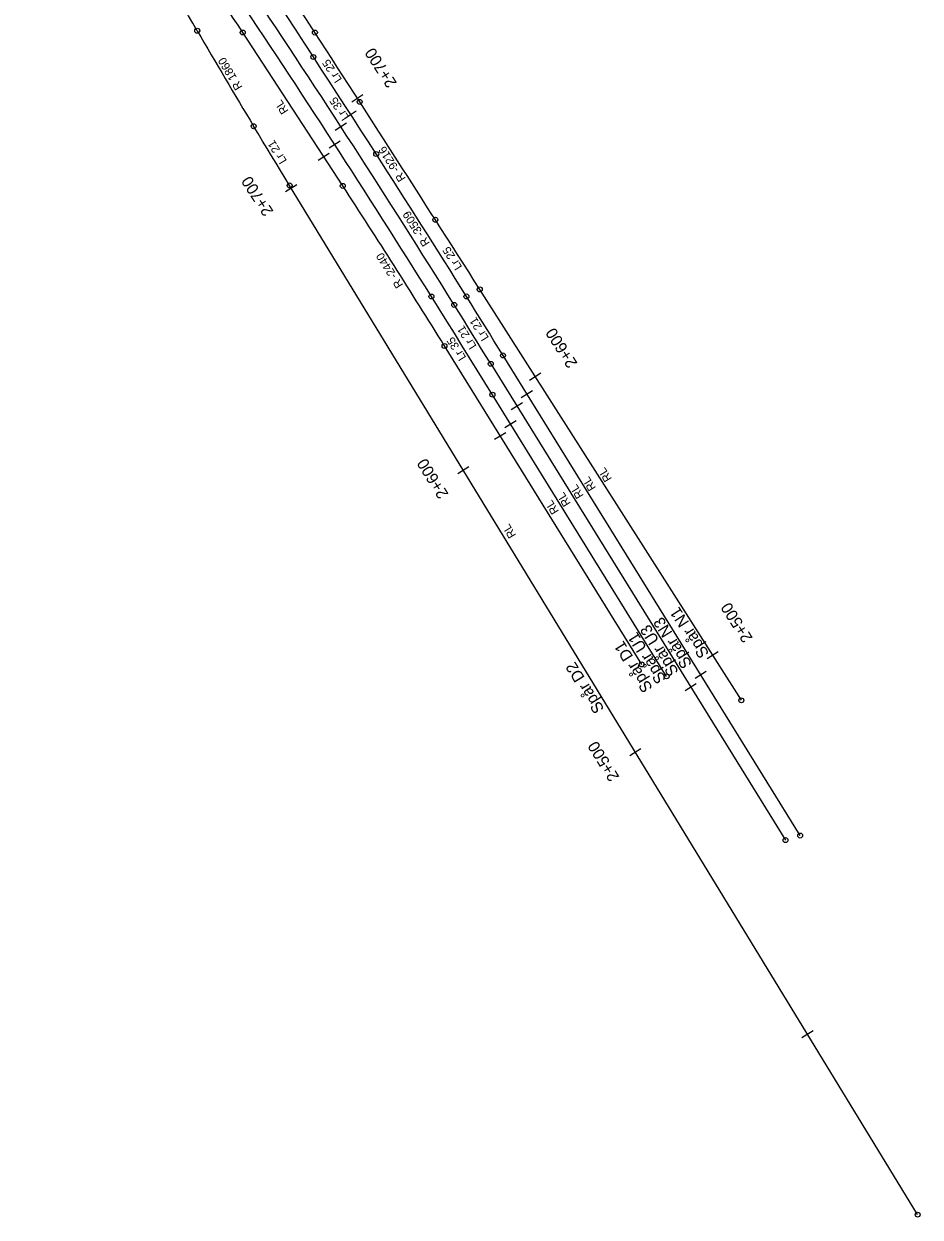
# Model space of a CAD drawing. Extents: x 149855 to 151460, y 6580726 to 6583068.
# Drawn here: x 151189 to 151460.4, y 6580725.5 to 6581086.8 of the extents above; entities that cross this region are included whole.
import ezdxf

# ---------------------------------------------------------------- set-up
doc = ezdxf.new("R2010")
doc.units = 0
for name, color, linetype in [('Hektometer L', 7, 'Continuous'), ('Hektometer T', 7, 'Continuous'), ('Modellutsnitt projekterat', 7, 'Continuous'), ('Spårgeometri T', 7, 'Continuous'), ('Spårmitt L', 7, 'Continuous'), ('Tp bef behålls P', 7, 'Continuous')]:
    doc.layers.add(name, color=color, linetype=linetype)

msp = doc.modelspace()

# ---------------------------------------------------------------- linework, layer by layer
at = {"layer": 'Hektometer L'}
for points in [[(151288.31, 6581063.21), (151291.67, 6581065.37)], [(151286.32, 6581058.25), (151289.68, 6581060.43)], [(151283.32, 6581054.6), (151286.68, 6581056.78)], [(151281.42, 6581049.24), (151284.78, 6581051.41)], [(151278.14, 6581045.51), (151281.49, 6581047.69)], [(151268.28, 6581036.03), (151271.69, 6581038.11)], [(151342.17, 6580978.96), (151345.54, 6580981.11)], [(151339.63, 6580973.7), (151343.03, 6580975.8)], [(151336.61, 6580970.03), (151340.01, 6580972.14)], [(151334.66, 6580964.64), (151338.06, 6580966.74)], [(151331.55, 6580961.02), (151334.95, 6580963.13)], [(151320.38, 6580950.67), (151323.79, 6580952.76)], [(151395.89, 6580894.62), (151399.26, 6580896.77)], [(151392.27, 6580888.67), (151395.67, 6580890.78)], [(151389.25, 6580885.01), (151392.65, 6580887.11)], [(151372.48, 6580865.32), (151375.89, 6580867.4)], [(151424.58, 6580779.96), (151427.99, 6580782.05)]]:
    msp.add_lwpolyline(points, dxfattribs=at)
at = {"layer": 'Spårmitt L'}
msp.add_line((151330.4, 6580983.87), (151419.65, 6580839.68), dxfattribs=at)
for points in [[(151277.13, 6581084.17), (151274.42, 6581088.37), (151271.7, 6581092.57), (151268.99, 6581096.77), (151266.27, 6581100.97), (151263.56, 6581105.17), (151260.86, 6581109.37), (151258.15, 6581113.58), (151255.45, 6581117.79), (151252.76, 6581122), (151250.07, 6581126.21), (151247.39, 6581130.43), (151244.71, 6581134.66), (151242.04, 6581138.89), (151239.38, 6581143.12)], [(151276.68, 6581076.77), (151273.95, 6581080.96), (151271.22, 6581085.15), (151268.5, 6581089.34), (151265.77, 6581093.54), (151263.05, 6581097.73), (151260.34, 6581101.93), (151257.62, 6581106.13), (151254.91, 6581110.33), (151252.21, 6581114.54), (151249.51, 6581118.74), (151246.82, 6581122.96), (151244.13, 6581127.17), (151241.45, 6581131.4), (151238.78, 6581135.62)], [(151241.52, 6581084.71), (151240.21, 6581086.99), (151238.9, 6581089.26), (151237.59, 6581091.54), (151236.29, 6581093.82), (151234.98, 6581096.09), (151233.68, 6581098.37), (151232.38, 6581100.65), (151231.08, 6581102.93)], [(151285.59, 6581037.74), (151255.29, 6581084.18)], [(151290.71, 6581063.18), (151289.01, 6581065.8), (151287.32, 6581068.43), (151285.62, 6581071.05), (151283.92, 6581073.68), (151282.23, 6581076.3), (151280.53, 6581078.92), (151278.83, 6581081.55), (151277.13, 6581084.17)], [(151295.72, 6581047.4), (151293.35, 6581051.08), (151290.97, 6581054.75), (151288.59, 6581058.43), (151286.21, 6581062.1), (151283.83, 6581065.77), (151281.45, 6581069.43), (151279.06, 6581073.1), (151276.68, 6581076.77)], [(151269.5, 6581037.87), (151268.13, 6581040.11), (151266.76, 6581042.35), (151265.39, 6581044.59), (151264.03, 6581046.83), (151262.67, 6581049.08), (151261.3, 6581051.32), (151259.95, 6581053.57), (151258.59, 6581055.81)], [(151459.68, 6580726.3), (151269.5, 6581037.87)], [(151327.06, 6581006.4), (151325.39, 6581009.04), (151323.71, 6581011.67), (151322.03, 6581014.31), (151320.35, 6581016.94), (151318.67, 6581019.58), (151316.99, 6581022.21), (151315.31, 6581024.85), (151313.63, 6581027.48)], [(151330.9, 6580974.52), (151328.6, 6580978.24), (151326.3, 6580981.96), (151323.99, 6580985.68), (151321.69, 6580989.4), (151319.38, 6580993.11), (151317.07, 6580996.83), (151314.75, 6581000.54), (151312.43, 6581004.25)], [(151334.11, 6580986.41), (151332.73, 6580988.64), (151331.35, 6580990.88), (151329.97, 6580993.11), (151328.58, 6580995.34), (151327.2, 6580997.57), (151325.82, 6580999.8), (151324.43, 6581002.03), (151323.04, 6581004.26)], [(151406.29, 6580882.01), (151327.06, 6581006.4)], [(151330.4, 6580983.87), (151329.02, 6580986.1), (151327.63, 6580988.33), (151326.25, 6580990.56), (151324.87, 6580992.79), (151323.49, 6580995.02), (151322.1, 6580997.25), (151320.71, 6580999.48), (151319.33, 6581001.71)], [(151376.11, 6580892.88), (151316.41, 6580989.27)], [(151424.1, 6580841.06), (151334.11, 6580986.41)], [(151383.65, 6580889.26), (151330.9, 6580974.52)], [(151459.68, 6580726.3), (151459.68, 6580726.3)]]:
    msp.add_lwpolyline(points, dxfattribs=at)
for centre, radius, start, end in [((148345.13, 6579148.16), 3504.5, 31.93168, 35.65829), ((148345.36, 6579147.78), 3500, 32.03381, 35.662), ((149580.27, 6579991.34), 2000, 33.12146, 34.32399), ((152851.64, 6582015.91), 1860, 210.04269, 211.07662), ((143546.99, 6576066.23), 9216, 32.570031, 32.833754), ((148345.03, 6579148.31), 3509, 31.93192, 32.76582), ((149242.06, 6579704.48), 2440, 31.77277, 33.12146)]:
    msp.add_arc(centre, radius, start, end, dxfattribs=at)
at = {"layer": 'Tp bef behålls P'}
for centre in [(151241.52, 6581084.71), (151255.29, 6581084.18), (151277.14, 6581084.16), (151276.68, 6581076.77), (151290.71, 6581063.17), (151258.59, 6581055.81), (151295.72, 6581047.4), (151269.5, 6581037.87), (151285.59, 6581037.74), (151313.63, 6581027.48), (151312.43, 6581004.25), (151323.04, 6581004.26), (151327.06, 6581006.4), (151319.33, 6581001.71), (151316.41, 6580989.27), (151334.11, 6580986.41), (151330.4, 6580983.87), (151330.9, 6580974.52), (151376.11, 6580892.88), (151383.65, 6580889.26), (151406.29, 6580882.01), (151424.1, 6580841.06), (151419.65, 6580839.68), (151459.68, 6580726.3)]:
    msp.add_circle(centre, 0.75, dxfattribs=at)

# ---------------------------------------------------------------- texts
at = {"layer": 'Hektometer T'}
for s, rotation, p in [('2+700', 122.8418, (151302.1, 6581068.88)), ('2+700', 122.928, (151264.73, 6581030.02)), ('2+600', 122.4923, (151356.78, 6580984.04)), ('2+600', 121.7473, (151317.72, 6580944.42)), ('2+500', 122.4923, (151409.85, 6580900.89)), ('2+500', 121.76, (151369.44, 6580858.81))]:
    msp.add_text(s, height=3.5, rotation=rotation, dxfattribs=at).set_placement(p)
at = {"layer": 'Modellutsnitt projekterat'}
for s, rotation, p in [('Spår N1', 122.9736, (151396.67, 6580896.18)), ('Spår N3', 122.0035, (151391.48, 6580892.96)), ('Spår U3', 121.8167, (151387.41, 6580890.65)), ('Spår D1', 121.8167, (151379.54, 6580885.71)), ('Spår U1', 121.8167, (151383.68, 6580888.38)), ('Spår D2', 121.8167, (151364.88, 6580879.37))]:
    msp.add_text(s, height=3.5, rotation=rotation, dxfattribs=at).set_placement(p)
at = {"layer": 'Spårgeometri T'}
for s, rotation, p in [('R 1860', 120.5597, (151255.29, 6581067.65)), ('Lr 25', 122.8856, (151285.43, 6581069.96)), ('RL', 122.9563, (151269.25, 6581060.44)), ('Lr 35', 122.9563, (151287.64, 6581058.52)), ('Lr 21', 121.2922, (151268.74, 6581045.34)), ('R -9216', 122.7019, (151304.73, 6581039.99)), ('R -3509', 122.3489, (151312.04, 6581020.4)), ('Lr 25', 122.5182, (151321.83, 6581013.22)), ('R -2440', 122.4471, (151303.97, 6581007.74)), ('Lr 21', 121.8176, (151329.91, 6580991.78)), ('Lr 21', 121.8172, (151326.19, 6580989.24)), ('Lr 35', 121.8428, (151323.04, 6580985.79)), ('RL', 121.8176, (151367.15, 6580949.08)), ('RL', 121.8176, (151358.63, 6580944)), ('RL', 121.8176, (151362.35, 6580946.34)), ('RL', 121.8176, (151351.13, 6580939.25)), ('RL', 121.8176, (151354.7, 6580941.61)), ('RL', 121.2922, (151338.16, 6580932))]:
    msp.add_text(s, height=2.5, rotation=rotation, dxfattribs=at).set_placement(p)

doc.saveas('drawing.dxf')
